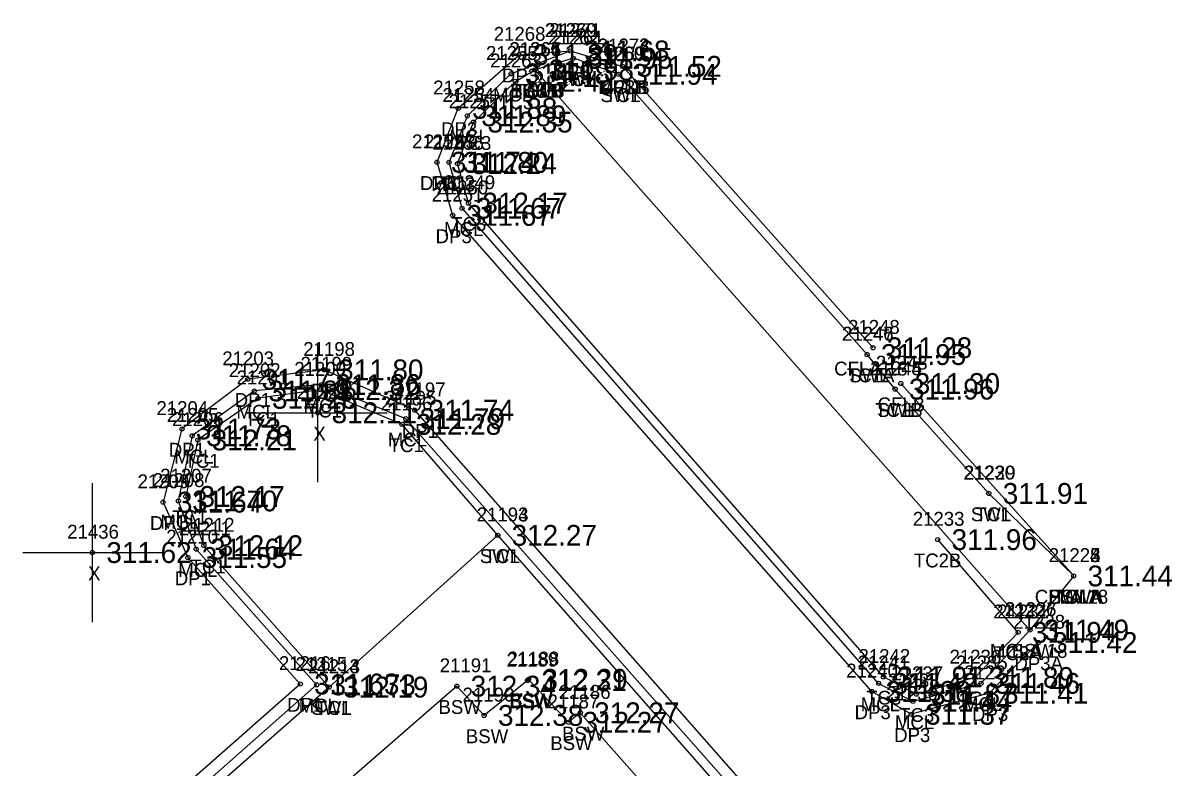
# Model space of a CAD drawing. Extents: x 1970242 to 1971082, y 803104 to 803947.
# Drawn here: x 1970328 to 1970410.7, y 803734.7 to 803788.3 of the extents above; entities that cross this region are included whole.
import ezdxf

# ---------------------------------------------------------------- set-up
doc = ezdxf.new("R2010")
doc.units = 0
for name, color, linetype in [('RD_DTM_BkLn2', 7, 'Continuous'), ('RD_EX_Conc', 7, 'Continuous'), ('RD_EX_Conc_txCode', 7, 'Continuous'), ('RD_EX_Driveway', 7, 'Continuous'), ('RD_EX_Driveway_txCode', 7, 'Continuous'), ('RD_EX_Misc', 7, 'Continuous'), ('RD_EX_Misc_txCode', 7, 'Continuous'), ('RD_EX_TX_Conc_ELEV', 7, 'Continuous'), ('RD_EX_TX_Driveway_ELEV', 7, 'Continuous'), ('RD_EX_TX_Misc_ELEV', 7, 'Continuous'), ('RD_SMD_Locator', 7, 'Continuous')]:
    doc.layers.add(name, color=color, linetype=linetype)

msp = doc.modelspace()

# ---------------------------------------------------------------- linework, layer by layer
at = {"layer": 'RD_DTM_BkLn2'}
msp.add_line((1970399.646, 803744.405), (1970393.856, 803751.08), dxfattribs=at)
for points in [[(1970388.776, 803764.406), (1970370.879, 803784.584), (1970367.637, 803785.738), (1970364.866, 803784.899)], [(1970399.646, 803744.405), (1970396.523, 803741.152), (1970392.323, 803739.953), (1970389.951, 803741.2), (1970360.09, 803775.312), (1970359.305, 803778.153), (1970360.455, 803781.141), (1970363.467, 803784.076), (1970364.866, 803784.899)], [(1970360.379, 803686.078), (1970364.002, 803689.27), (1970372.797, 803697.031), (1970384.031, 803706.942), (1970388.043, 803714.574), (1970387.812, 803720.9), (1970384.41, 803726.133), (1970362.198, 803751.392), (1970355.314, 803759.382), (1970349.43, 803761.874), (1970344.957, 803761.259), (1970340.617, 803758.255), (1970339.742, 803754.187), (1970341.052, 803750.645), (1970350.072, 803740.463), (1970336.455, 803728.473)], [(1970403.64, 803748.467), (1970397.536, 803754.406), (1970390.789, 803761.917)]]:
    msp.add_lwpolyline(points, dxfattribs=at)
at = {"layer": 'RD_EX_Conc'}
for p, q in [((1970389.201, 803764.895), (1970371.192, 803785.158)), ((1970403.64, 803748.467), (1970391.208, 803762.321))]:
    msp.add_line(p, q, dxfattribs=at)
for points in [[(1970400.496, 803744.573), (1970396.967, 803740.732), (1970392.069, 803739.438), (1970389.604, 803740.729), (1970359.627, 803774.94), (1970358.692, 803778.244), (1970360.013, 803781.594), (1970363.147, 803784.619), (1970367.42, 803786.267), (1970371.192, 803785.158)], [(1970403.64, 803748.467), (1970397.536, 803754.406), (1970390.789, 803761.917), (1970388.776, 803764.406), (1970370.879, 803784.584), (1970367.637, 803785.738), (1970364.866, 803784.899)], [(1970403.64, 803748.467), (1970400.496, 803744.573), (1970364.866, 803784.899)], [(1970360.928, 803685.78), (1970384.619, 803706.625), (1970388.613, 803714.286), (1970388.403, 803721.009), (1970384.878, 803726.626), (1970355.578, 803759.79), (1970349.519, 803762.244), (1970344.685, 803761.785), (1970340.214, 803758.559), (1970339.209, 803753.867), (1970340.497, 803750.4), (1970349.163, 803740.623), (1970336.054, 803729.022)], [(1970388.043, 803714.574), (1970387.812, 803720.9), (1970384.41, 803726.133), (1970362.198, 803751.392), (1970350.072, 803740.463), (1970336.455, 803728.473)], [(1970388.043, 803714.574), (1970384.866, 803718.144), (1970385.631, 803718.829), (1970368.137, 803738.615), (1970367.294, 803737.93), (1970364.409, 803741.02), (1970364.338, 803740.936), (1970361.218, 803738.424), (1970359.252, 803740.53), (1970341.72, 803725.277)]]:
    msp.add_lwpolyline(points, dxfattribs=at)
at = {"layer": 'RD_EX_Driveway'}
for points in [[(1970401.094, 803743.669), (1970397.555, 803740.019), (1970391.952, 803738.507), (1970389.106, 803740.151), (1970358.957, 803774.425), (1970357.83, 803778.256), (1970359.349, 803782.137), (1970363.728, 803785.997), (1970367.42, 803786.267), (1970367.42, 803786.267), (1970371.192, 803785.158)], [(1970361.584, 803685.25), (1970385.155, 803706.07), (1970389.475, 803713.845), (1970389.303, 803721.405), (1970385.523, 803727.117), (1970356.232, 803760.398), (1970349.717, 803763.304), (1970344.215, 803762.632), (1970339.473, 803759.052), (1970338.114, 803753.777), (1970339.901, 803749.792), (1970347.988, 803740.685), (1970335.512, 803729.688)]]:
    msp.add_lwpolyline(points, dxfattribs=at)
at = {"layer": 'RD_EX_Misc'}
for p, q in [((1970349.243, 803755.213), (1970349.243, 803765.213)), ((1970344.243, 803760.213), (1970354.243, 803760.213)), ((1970333.035, 803745.15), (1970333.035, 803755.15)), ((1970328.035, 803750.15), (1970338.035, 803750.15))]:
    msp.add_line(p, q, dxfattribs=at)
at = {"layer": 'RD_SMD_Locator'}
for centre in [(1970367.42, 803786.267), (1970367.42, 803786.267), (1970367.42, 803786.267), (1970363.728, 803785.997), (1970367.637, 803785.738), (1970367.637, 803785.738), (1970363.147, 803784.619), (1970364.866, 803784.899), (1970364.866, 803784.899), (1970364.866, 803784.899), (1970364.866, 803784.899), (1970370.879, 803784.584), (1970370.879, 803784.584), (1970371.192, 803785.158), (1970371.192, 803785.158), (1970371.192, 803785.158), (1970363.467, 803784.076), (1970359.349, 803782.137), (1970360.013, 803781.594), (1970360.455, 803781.141), (1970357.83, 803778.256), (1970358.692, 803778.244), (1970359.305, 803778.153), (1970359.627, 803774.94), (1970360.09, 803775.312), (1970358.957, 803774.425), (1970389.201, 803764.895), (1970388.776, 803764.406), (1970388.776, 803764.406), (1970349.717, 803763.304), (1970344.215, 803762.632), (1970349.519, 803762.244), (1970391.208, 803762.321), (1970344.685, 803761.785), (1970349.43, 803761.874), (1970390.789, 803761.917), (1970390.789, 803761.917), (1970344.957, 803761.259), (1970349.243, 803760.213), (1970355.578, 803759.79), (1970356.232, 803760.398), (1970339.473, 803759.052), (1970355.314, 803759.382), (1970340.214, 803758.559), (1970340.617, 803758.255), (1970339.742, 803754.187), (1970397.536, 803754.406), (1970397.536, 803754.406), (1970338.114, 803753.777), (1970339.209, 803753.867), (1970341.052, 803750.645), (1970362.198, 803751.392), (1970362.198, 803751.392), (1970393.856, 803751.08), (1970333.035, 803750.15), (1970339.901, 803749.792), (1970340.497, 803750.4), (1970403.64, 803748.467), (1970403.64, 803748.467), (1970403.64, 803748.467), (1970403.64, 803748.467), (1970399.646, 803744.405), (1970399.646, 803744.405), (1970400.496, 803744.573), (1970400.496, 803744.573), (1970401.094, 803743.669), (1970347.988, 803740.685), (1970364.338, 803740.936), (1970364.409, 803741.02), (1970389.604, 803740.729), (1970389.951, 803741.2), (1970396.523, 803741.152), (1970396.967, 803740.732), (1970349.163, 803740.623), (1970350.072, 803740.463), (1970350.072, 803740.463), (1970359.252, 803740.53), (1970389.106, 803740.151), (1970392.323, 803739.953), (1970397.555, 803740.019), (1970392.069, 803739.438), (1970361.218, 803738.424), (1970368.137, 803738.615), (1970391.952, 803738.507), (1970367.294, 803737.93)]:
    msp.add_circle(centre, 0.15, dxfattribs=at)

# ---------------------------------------------------------------- texts
at = {"layer": 'RD_EX_Conc_txCode'}
for s, p in [('21271', (1970365.908, 803787.267)), ('21262', (1970365.818, 803786.738)), ('21261', (1970366.101, 803786.738)), ('21272', (1970369.396, 803786.158)), ('21273', (1970369.396, 803786.158)), ('21255', (1970361.352, 803785.619)), ('21266', (1970363.023, 803785.899)), ('21264', (1970363.047, 803785.899)), ('21265', (1970363.047, 803785.899)), ('21267', (1970363.047, 803785.899)), ('21260', (1970369.021, 803785.584)), ('21259', (1970369.084, 803785.584)), ('21263', (1970361.648, 803785.076)), ('MCL', (1970366.129, 803784.267)), ('SWL', (1970366.345, 803783.738)), ('TC1', (1970366.676, 803783.738)), ('SWLB', (1970363.102, 803782.899)), ('TC3B', (1970363.149, 803782.899)), ('BSWB', (1970363.078, 803782.899)), ('TC1B', (1970363.433, 803782.899)), ('MCLB', (1970369.428, 803783.158)), ('CFLB', (1970369.514, 803783.158)), ('21254', (1970358.218, 803782.594)), ('21257', (1970358.66, 803782.141)), ('MCL', (1970361.856, 803782.619)), ('TC3', (1970362.222, 803782.076)), ('SWL', (1970369.588, 803782.584)), ('TC1', (1970369.918, 803782.584)), ('MCL', (1970358.722, 803779.594)), ('21253', (1970356.897, 803779.244)), ('21256', (1970357.486, 803779.153)), ('TC3', (1970359.211, 803779.141)), ('MCL', (1970357.401, 803776.244)), ('21249', (1970358.294, 803776.312)), ('21250', (1970357.793, 803775.94)), ('TC3', (1970358.061, 803776.153)), ('MCL', (1970358.336, 803772.94)), ('TC3', (1970358.846, 803773.312)), ('21248', (1970387.405, 803765.895)), ('21246', (1970386.957, 803765.406)), ('21247', (1970386.98, 803765.406)), ('21199', (1970348.007, 803763.244)), ('21243', (1970389.412, 803763.321)), ('21202', (1970342.85, 803762.785)), ('21201', (1970343.406, 803762.259)), ('21200', (1970347.556, 803762.874)), ('CFLA 18', (1970386.405, 803762.895)), ('TC1A', (1970387.327, 803762.406)), ('SWL', (1970387.484, 803762.406)), ('21244', (1970388.994, 803762.917)), ('21245', (1970388.994, 803762.917)), ('21195', (1970354.066, 803760.79)), ('MCL', (1970343.394, 803759.785)), ('MCL', (1970348.227, 803760.244)), ('TC1', (1970348.469, 803759.874)), ('21196', (1970353.779, 803760.382)), ('TC1B', (1970389.356, 803759.917)), ('SWL', (1970389.498, 803759.917)), ('CFLB', (1970389.53, 803760.321)), ('21205', (1970338.379, 803759.559)), ('21206', (1970338.758, 803759.255)), ('TC1', (1970343.996, 803759.259)), ('TC1', (1970354.353, 803757.382)), ('MCL', (1970354.287, 803757.79)), ('MCL', (1970338.922, 803756.559)), ('TC1', (1970339.656, 803756.255)), ('21208', (1970337.374, 803754.867)), ('21207', (1970337.907, 803755.187)), ('21230', (1970395.701, 803755.406)), ('21229', (1970395.741, 803755.406)), ('21193', (1970360.686, 803752.392)), ('21194', (1970360.686, 803752.392)), ('SWL', (1970396.245, 803752.406)), ('TC1', (1970396.575, 803752.406)), ('MCL', (1970337.918, 803751.867)), ('TC1', (1970338.781, 803752.187)), ('21211', (1970339.268, 803751.4)), ('21212', (1970339.54, 803751.645)), ('21233', (1970392.061, 803752.08)), ('SWL', (1970360.907, 803749.392)), ('TC1', (1970361.237, 803749.392)), ('TC2B', (1970392.139, 803749.08)), ('21222', (1970401.844, 803749.467)), ('21223', (1970401.844, 803749.467)), ('21224', (1970401.844, 803749.467)), ('21225', (1970401.844, 803749.467)), ('MCL', (1970339.205, 803748.4)), ('TC1', (1970340.091, 803748.645)), ('CFLA 18', (1970400.844, 803746.467)), ('SWLA', (1970401.86, 803746.467)), ('BSWA', (1970401.836, 803746.467)), ('TC1A', (1970402.191, 803746.467)), ('21232', (1970397.85, 803745.405)), ('21231', (1970398.134, 803745.405)), ('21226', (1970398.677, 803745.573)), ('21227', (1970398.7, 803745.573)), ('MCLA 18', (1970397.614, 803742.573)), ('TC2A', (1970397.913, 803742.405)), ('TC3A', (1970397.913, 803742.405)), ('BSW', (1970399.181, 803742.573)), ('21215', (1970347.651, 803741.623)), ('21191', (1970358.024, 803741.53)), ('21189', (1970362.827, 803741.936)), ('21188', (1970362.898, 803742.02)), ('21241', (1970388.092, 803741.729)), ('21242', (1970388.155, 803742.2)), ('21236', (1970394.704, 803742.152)), ('21235', (1970395.171, 803741.732)), ('21213', (1970348.56, 803741.463)), ('21214', (1970348.56, 803741.463)), ('21237', (1970390.528, 803740.953)), ('21238', (1970390.274, 803740.438)), ('21190', (1970359.667, 803739.424)), ('BSW', (1970363.094, 803739.02)), ('21186', (1970366.601, 803739.615)), ('TC3', (1970388.707, 803739.2)), ('TC3', (1970395.279, 803739.152)), ('MCL', (1970347.871, 803738.623)), ('SWL', (1970348.781, 803738.463)), ('TC1', (1970349.111, 803738.463)), ('BSW', (1970357.937, 803738.53)), ('BSW', (1970363.023, 803738.936)), ('21187', (1970365.782, 803738.93)), ('MCL', (1970388.313, 803738.729)), ('MCL', (1970395.675, 803738.732)), ('MCL', (1970390.778, 803737.438)), ('TC3', (1970391.079, 803737.953)), ('BSW', (1970366.822, 803736.615)), ('BSW', (1970359.903, 803736.424)), ('BSW', (1970365.979, 803735.93))]:
    msp.add_text(s, height=1, dxfattribs=at).set_placement(p)
at = {"layer": 'RD_EX_Driveway_txCode'}
for s, p in [('21268', (1970361.909, 803786.997)), ('21270', (1970365.585, 803787.267)), ('21269', (1970365.601, 803787.267)), ('21274', (1970369.396, 803786.158)), ('DP3', (1970362.499, 803783.997)), ('DP3', (1970366.192, 803784.267)), ('DP3', (1970366.192, 803784.267)), ('21258', (1970357.554, 803783.137)), ('DP3B', (1970369.491, 803783.158)), ('DP3', (1970358.121, 803780.137)), ('21252', (1970356.034, 803779.256)), ('DP3', (1970356.601, 803776.256)), ('21251', (1970357.445, 803775.425)), ('DP3', (1970357.728, 803772.425)), ('21198', (1970348.205, 803764.304)), ('21203', (1970342.38, 803763.632)), ('21197', (1970354.72, 803761.398)), ('DP1', (1970343.27, 803760.632)), ('DP1', (1970348.772, 803761.304)), ('21204', (1970337.638, 803760.052)), ('DP1', (1970355.287, 803758.398)), ('DP1', (1970338.528, 803757.052)), ('21209', (1970336.279, 803754.777)), ('DP1', (1970337.169, 803751.777)), ('21210', (1970338.349, 803750.792)), ('DP1', (1970338.956, 803747.792)), ('21228', (1970399.299, 803744.669)), ('21216', (1970346.453, 803741.685)), ('DP3A', (1970399.378, 803741.669)), ('21240', (1970387.271, 803741.151)), ('21234', (1970395.759, 803741.019)), ('21239', (1970390.157, 803739.507)), ('DP1', (1970347.043, 803738.685)), ('DP3', (1970387.877, 803738.151)), ('DP3', (1970396.326, 803738.019)), ('DP3', (1970390.723, 803736.507))]:
    msp.add_text(s, height=1, dxfattribs=at).set_placement(p)
at = {"layer": 'RD_EX_Misc_txCode'}
for s, p in [('21221', (1970347.732, 803761.213)), ('X', (1970348.928, 803758.213)), ('21436', (1970331.216, 803751.15)), ('X', (1970332.72, 803748.15))]:
    msp.add_text(s, height=1, dxfattribs=at).set_placement(p)
at = {"layer": 'RD_EX_TX_Conc_ELEV'}
for s, p in [('311.68', (1970368.42, 803785.517)), ('311.95', (1970368.637, 803784.988)), ('311.95', (1970368.637, 803784.988)), ('311.98', (1970365.866, 803784.149)), ('311.98', (1970365.866, 803784.149)), ('311.98', (1970365.866, 803784.149)), ('311.98', (1970365.866, 803784.149)), ('311.52', (1970372.192, 803784.408)), ('311.52', (1970372.192, 803784.408)), ('311.98', (1970364.147, 803783.869)), ('312.42', (1970364.467, 803783.326)), ('311.94', (1970371.879, 803783.834)), ('311.94', (1970371.879, 803783.834)), ('311.89', (1970361.013, 803780.844)), ('312.35', (1970361.455, 803780.391)), ('311.80', (1970359.692, 803777.494)), ('312.24', (1970360.305, 803777.403)), ('311.67', (1970360.627, 803774.19)), ('312.17', (1970361.09, 803774.562)), ('311.28', (1970390.201, 803764.145)), ('311.95', (1970389.776, 803763.656)), ('311.95', (1970389.776, 803763.656)), ('311.83', (1970345.685, 803761.035)), ('312.32', (1970350.43, 803761.124)), ('311.86', (1970350.519, 803761.494)), ('311.96', (1970391.789, 803761.167)), ('311.96', (1970391.789, 803761.167)), ('311.30', (1970392.208, 803761.571)), ('312.28', (1970345.957, 803760.509)), ('312.28', (1970356.314, 803758.632)), ('311.79', (1970356.578, 803759.04)), ('311.78', (1970341.214, 803757.809)), ('312.21', (1970341.617, 803757.505)), ('312.17', (1970340.742, 803753.437)), ('311.91', (1970398.536, 803753.656)), ('311.91', (1970398.536, 803753.656)), ('311.70', (1970340.209, 803753.117)), ('312.27', (1970363.198, 803750.642)), ('312.27', (1970363.198, 803750.642)), ('311.96', (1970394.856, 803750.33)), ('311.64', (1970341.497, 803749.65)), ('312.12', (1970342.052, 803749.895)), ('311.44', (1970404.64, 803747.717)), ('311.44', (1970404.64, 803747.717)), ('311.44', (1970404.64, 803747.717)), ('311.44', (1970404.64, 803747.717)), ('311.94', (1970400.646, 803743.655)), ('311.94', (1970400.646, 803743.655)), ('311.49', (1970401.496, 803743.823)), ('311.49', (1970401.496, 803743.823)), ('312.31', (1970365.338, 803740.186)), ('312.29', (1970365.409, 803740.27)), ('311.91', (1970390.951, 803740.45)), ('311.89', (1970397.523, 803740.402)), ('311.73', (1970350.163, 803739.873)), ('312.19', (1970351.072, 803739.713)), ('312.19', (1970351.072, 803739.713)), ('312.34', (1970360.252, 803739.78)), ('311.42', (1970390.604, 803739.979)), ('311.46', (1970397.967, 803739.982)), ('311.44', (1970393.069, 803738.688)), ('311.87', (1970393.323, 803739.203)), ('312.38', (1970362.218, 803737.674)), ('312.27', (1970369.137, 803737.865)), ('312.27', (1970368.294, 803737.18))]:
    msp.add_text(s, height=1.5, dxfattribs=at).set_placement(p)
at = {"layer": 'RD_EX_TX_Driveway_ELEV'}
for s, p in [('311.89', (1970364.728, 803785.247)), ('311.68', (1970368.42, 803785.517)), ('311.68', (1970368.42, 803785.517)), ('311.52', (1970372.192, 803784.408)), ('311.88', (1970360.349, 803781.387)), ('311.74', (1970358.83, 803777.506)), ('311.67', (1970359.957, 803773.675)), ('311.80', (1970350.717, 803762.554)), ('311.77', (1970345.215, 803761.882)), ('311.74', (1970357.232, 803759.648)), ('311.73', (1970340.473, 803758.302)), ('311.64', (1970339.114, 803753.027)), ('311.55', (1970340.901, 803749.042)), ('311.42', (1970402.094, 803742.919)), ('311.63', (1970348.988, 803739.935)), ('311.38', (1970390.106, 803739.401)), ('311.41', (1970398.555, 803739.269)), ('311.37', (1970392.952, 803737.757))]:
    msp.add_text(s, height=1.5, dxfattribs=at).set_placement(p)
at = {"layer": 'RD_EX_TX_Misc_ELEV'}
for s, p in [('312.11', (1970350.243, 803759.463)), ('311.62', (1970334.035, 803749.4))]:
    msp.add_text(s, height=1.5, dxfattribs=at).set_placement(p)

doc.saveas('drawing.dxf')
